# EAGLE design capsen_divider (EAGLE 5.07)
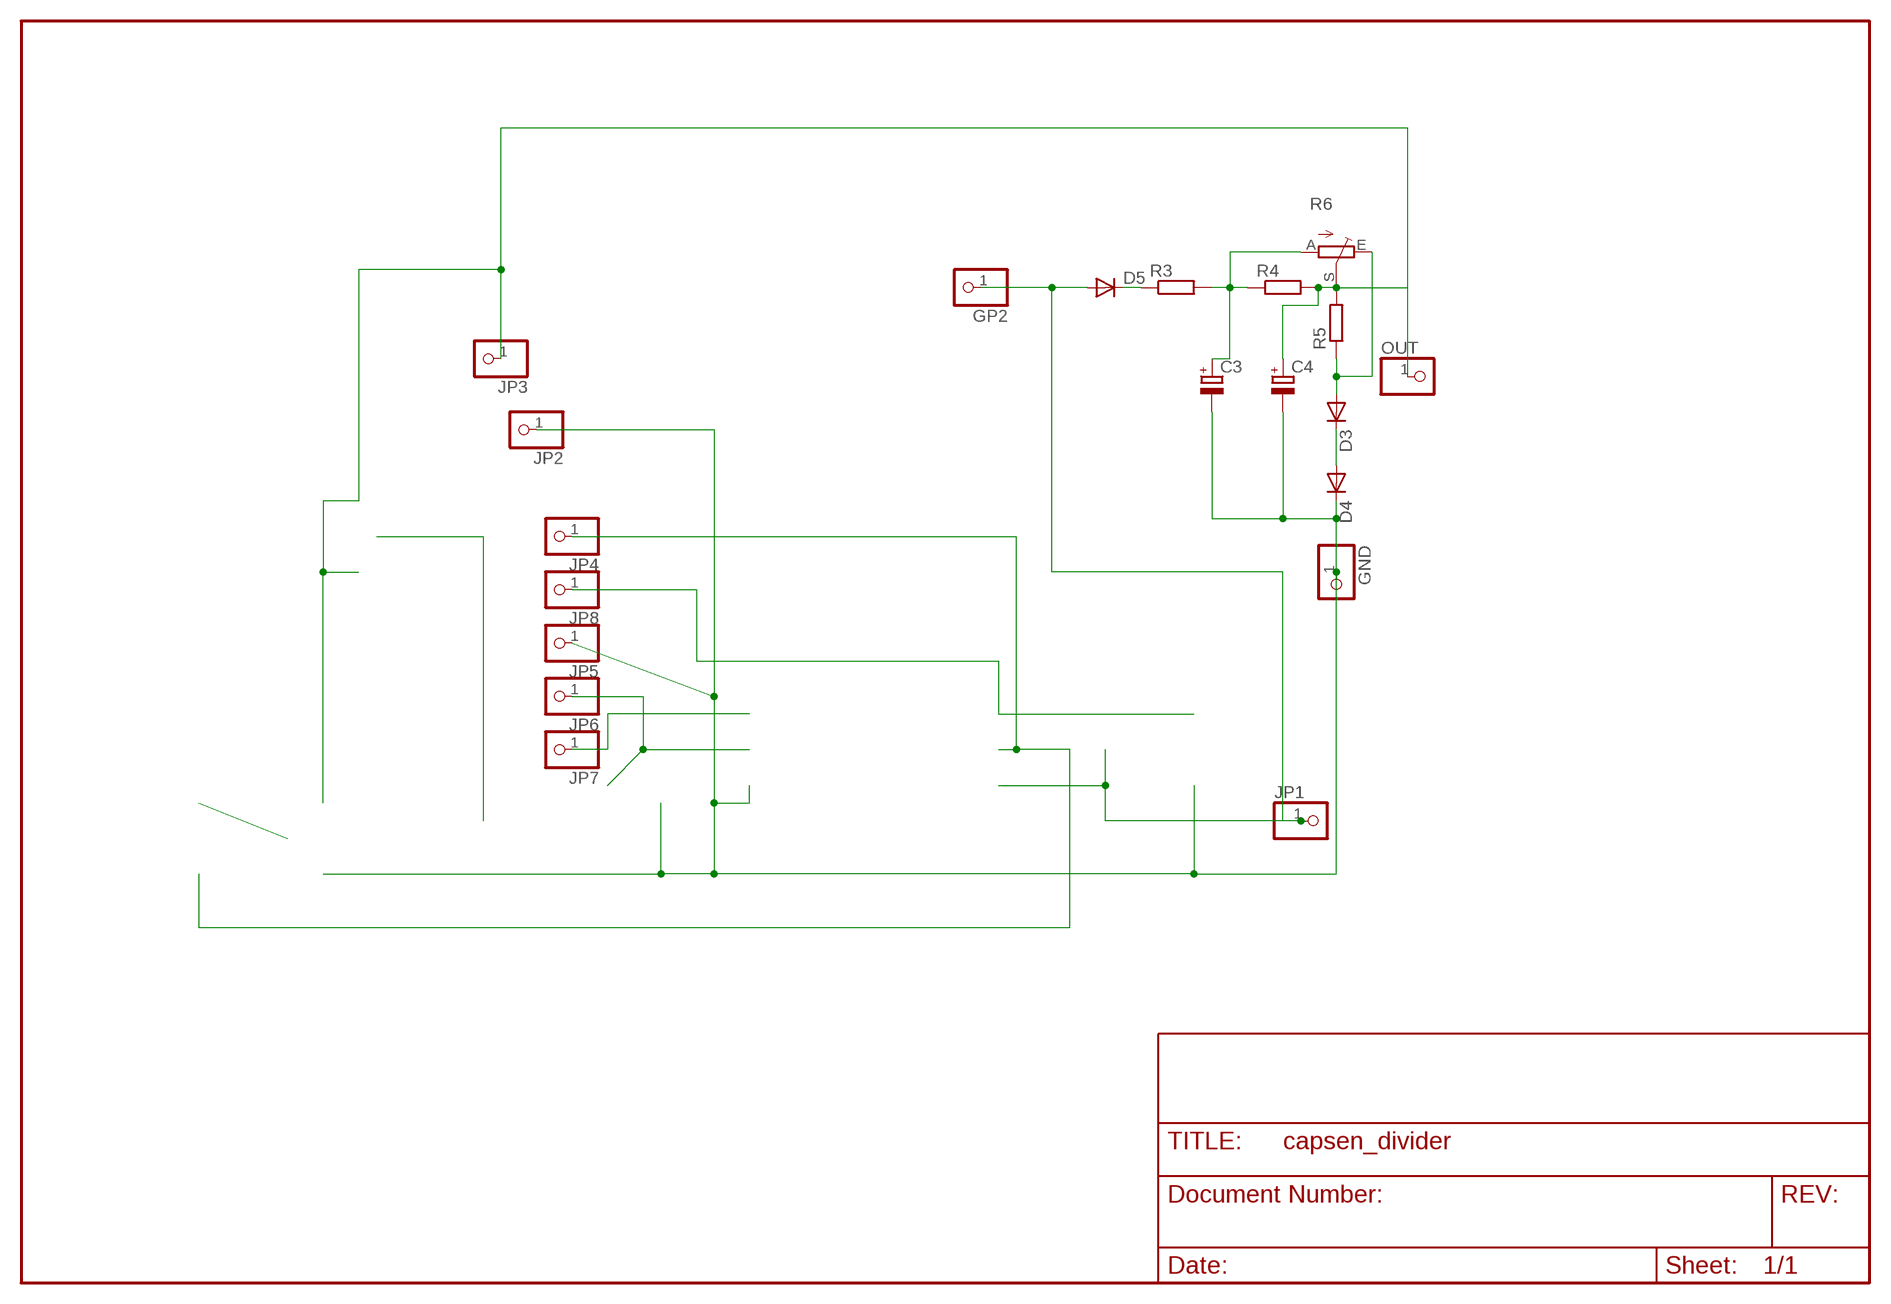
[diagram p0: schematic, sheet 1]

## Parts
C3  CPOL-EUSMCA  [SMC_A]
C4  CPOL-EUSMCA  [SMC_A]
D3  DIODE-SOD80C  [SOD80C]
D4  DIODE-SOD80C  [SOD80C]
D5  DIODE-SOD80C  [SOD80C]
GND  PINHD-1X11X0.4  [1X01]
GP2  PINHD-1X11X0.4  [1X01]
JP1  PINHD-1X1  [1X01]
JP2  PINHD-1X1  [1X01]
JP3  PINHD-1X1  [1X01]
JP4  PINHD-1X1  [1X01]
JP5  PINHD-1X1  [1X01]
JP6  PINHD-1X1  [1X01]
JP7  PINHD-1X1  [1X01]
JP8  PINHD-1X1  [1X01]
OUT  PINHD-1X11X0.4  [1X01]
R3  R-EU_R0805  [R0805]
R4  R-EU_R0805  [R0805]
R5  R-EU_R0805  [R0805]
R6  TRIM_EU-CA6V  [CA6V]

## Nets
DR1: D5.C R3.1
DR2: D3.A R5.1 R6.E
GND: C3.- C4.- D4.C GND.1 JP2.1 JP5.1
GP0: JP8.1
GP1: JP4.1
GP2: D5.A GP2.1 JP1.1
GP3: JP7.1
N$2: D3.C D4.A
N$5: JP6.1
OUT: C4.+ JP3.1 OUT.1 R4.2 R5.2 R6.S
RRC: C3.+ R3.2 R4.1 R6.A

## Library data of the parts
C3 C4 = rcl:CPOL-EU: POLARIZED CAPACITOR, European symbol
D3-D5 = diode:DIODE-: DIODE
GND GP2 OUT = pinhead:PINHD-1X1: PIN HEADER
JP1-JP8 = pinhead(2):PINHD-1X1: PIN HEADER
R3-R5 = rcl:R-EU_: RESISTOR, European symbol
R6 = pot:TRIM_EU-: POTENTIOMETER

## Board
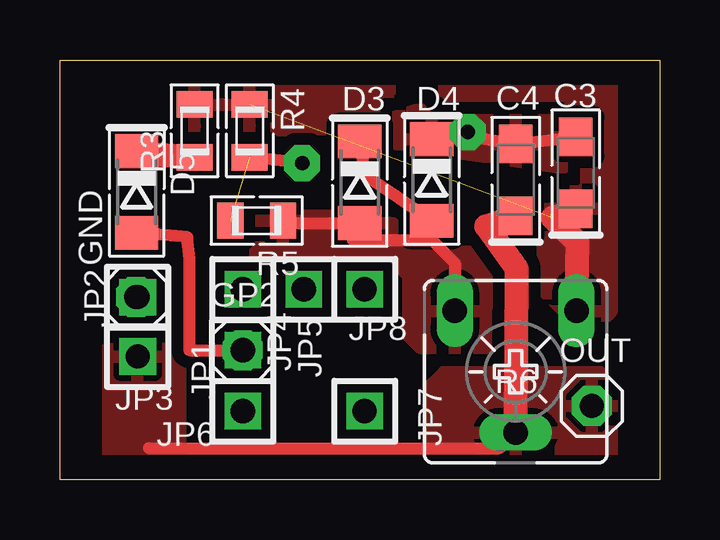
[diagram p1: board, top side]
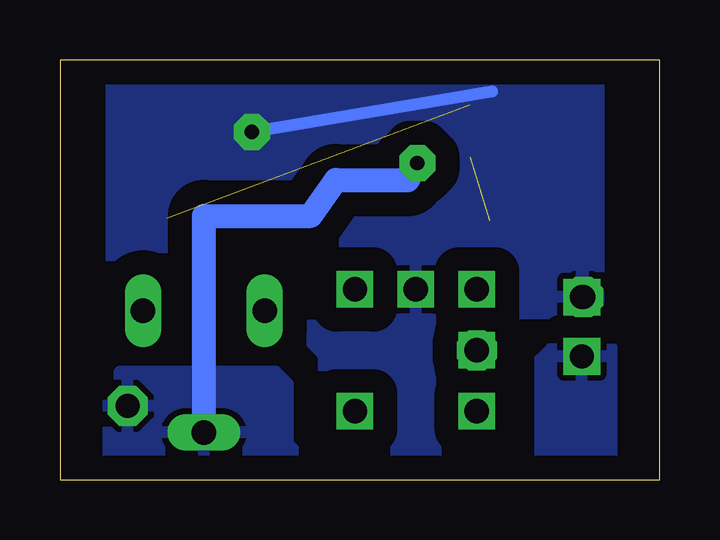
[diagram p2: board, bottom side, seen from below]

Size 25 x 17.5 mm. Coordinates in mm from the lower left corner, seen from the top.
Outline: 0,0 0,17.5 25,17.5 25,0 0,0
Copper layers (1*16): Top 0.035mm / dielectric 1.5mm / Bottom 0.035mm
Design rules "default": minimum track width 10mil, minimum drill 24mil, track to track 8mil, track to pad 8mil, pad to pad 8mil, via to via 8mil, smd to smd 8mil, copper to edge 40mil, drill to drill 8mil, minimum pad ring 10mil, minimum via ring 8mil, stop-mask expansion 4mil, vias tented up to drill 0mil, thermal gap 10mil

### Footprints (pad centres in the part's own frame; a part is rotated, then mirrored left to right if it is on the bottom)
SMC_A = smd 1.6 x 1.4: + -1.5,0; - 1.5,0
SOD80C = smd 1.4 x 1.8: A 1.7,0; C -1.7,0
1X01 = drill 1 pad 1.676 octagon: 1 0,0
1X01' = drill 1.016 square: 1 0,0
R0805 = smd 1.1 x 1.5: 1 -1.1,0; 2 1.1,0
CA6V = drill 1.016 long: A -2.54,-2.54; E 2.54,-2.54; S 0,2.54

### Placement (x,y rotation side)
C3  21.5,12.8 90 top
C4  19,12.5 90 top
D3  12.5,12.4 270 top
D4  15.5,12.5 270 top
D5  3.2,12 270 top
GND  3.17,7.61 0 top
GP2  7.62,5.39 0 top
JP1  [1X01']  7.62,5.39 90 top
JP2  [1X01']  3.24,7.61 90 top
JP3  [1X01']  3.24,5.14 90 top
JP4  [1X01']  7.62,7.93 0 top
JP5  [1X01']  10.16,7.93 0 top
JP6  [1X01']  7.62,2.85 0 top
JP7  [1X01']  12.7,2.85 0 top
JP8  [1X01']  12.7,7.93 0 top
OUT  22.18,3.07 0 top
R3  5.62,14.54 90 top
R4  7.92,14.54 270 top
R5  8.2,10.8 180 top
R6  19,4.5 180 top

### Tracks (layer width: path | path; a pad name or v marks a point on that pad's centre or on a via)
DR1
  Top 1: D5.C 3.58,13.59 R3.1
DR2
  Top 0.5: R6.E 16.46,9.04 15.5,10 12.2,10 D3.A 9.2,10.7 R5.1
  pour Top (isolate 0.5, rank 3): 18,5.5 18,10.5 16.5,11 7.5,11 7.5,9.5 13.5,9.5 14.5,8.5 14.5,6 15,5.5
GND  (via drill 0.6 pad 1.5)
  Top 0.5: v17,14.5 15.9,14.62 D4.C 16.57,14.41 C4.- C3.-
  Bottom 0.5: 6.99,16.18 v17,14.5
  pour Bottom (isolate 1, rank 3): 2.54,16.82 22.86,16.82 22.86,-0.96 2.54,-0.96
  pour Top (isolate 0.5): 13.5,15 13.5,14.5 14,14 21,13 20.5,15 15.5,15 15,15.5
GP2
  Top 0.5: GP2.1 5.4,5.39 5.4,9.2 5.31,10.11 D5.A
N$2
  Top 0.5: D4.A 12.7,12.71 D3.C
OUT  (via drill 0.6 pad 1.5)  (1 unrouted)
  Top 0.5: 3.71,1.31 18.32,1.31 19.05,1.95 R6.S | v10.1,13.2 R4.2
  Top 1: R6.S 19.05,8.79 17.78,10.56 C4.+
  Bottom 1: v10.1,13.2 10.5,12.48 13.5,12.5 14.55,11 C4.+ R6.S
  pour Top (isolate 0.5, rank 2): 16,4.5 22.5,4.5 23,4 23,-0.5 22.5,-1 2.5,-1 2,-0.5 2,5.5 4.5,5.5 5,5 5,1 15,1 15.5,1.5 15.5,4
  pour Bottom (isolate 0.5, rank 2): 16,4.5 22.5,4.5 23,4 23,-0.5 22.5,-1 2.5,-1 2,-0.5 2,5.5 4.5,5.5 5,5 5,1 15,1 15.5,1.5 15.5,4
RRC  (1 unrouted)
  Top 1: R6.A 21.59,9.88 20.55,10.91 C3.+
  pour Top (isolate 0.5, rank 2): 6,17 22.5,17 23,16.5 23,7 22.5,6.5 21.5,6.5 20,8 20,14.5 9.5,14.5 8,13.5 5.5,13.5 5.5,16.5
